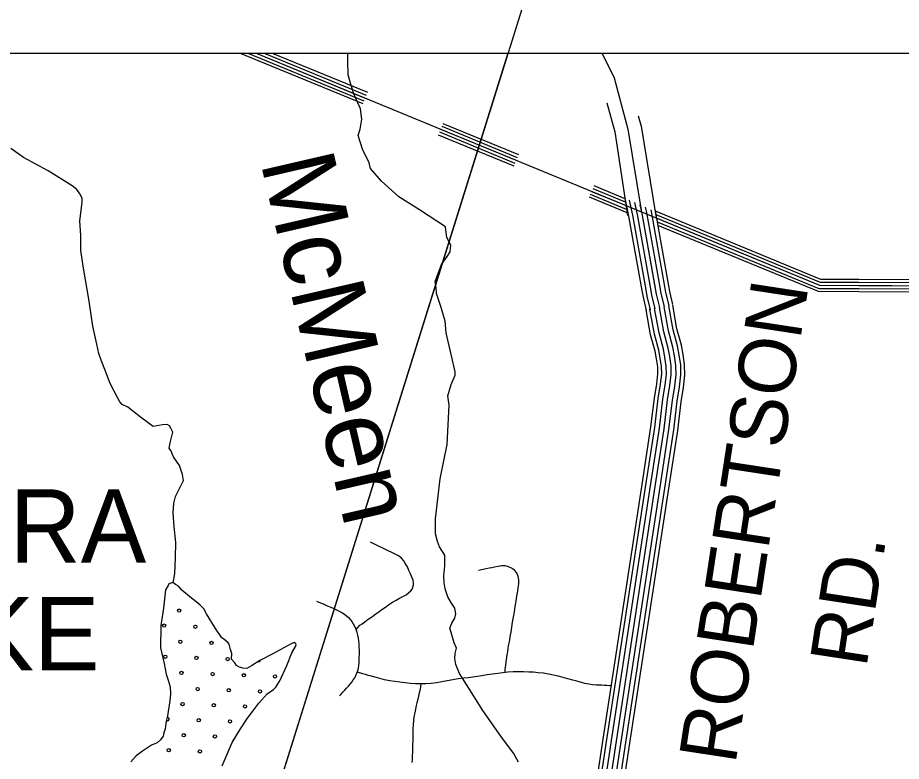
# Model space of a CAD drawing. Extents: x 1577619 to 1828281, y 483481 to 598136.
# Drawn here: x 1675660 to 1681374, y 521931 to 526740 of the extents above; entities that cross this region are included whole.
import ezdxf

# ---------------------------------------------------------------- set-up
doc = ezdxf.new("R2010")
doc.units = 0
for name, color, linetype in [('DESIGN - DRAINAGE - Bridges and Cross Drains Size Text', 7, 'Continuous'), ('DESIGN - ROW - Right-of-Way and Easement Labels', 7, 'Continuous'), ('DESIGN - SHEET - Linework', 7, 'Continuous'), ('DESIGN - TRAFFIC CONTROL PERMANENT - Pavement Marking Text', 7, 'Continuous'), ('DESIGN - TRANSPORTATION - Text', 7, 'Continuous'), ('SURVEY - CENTERLINE - Preliminary Text', 7, 'Continuous'), ('SURVEY - DRAINAGE - Natural Features', 7, 'Continuous'), ('SURVEY - PROPERTY - Owners', 7, 'Continuous'), ('SURVEY - TRANSPORTATION - Roads', 7, 'Continuous')]:
    doc.layers.add(name, color=color, linetype=linetype)

msp = doc.modelspace()

# ---------------------------------------------------------------- linework, layer by layer
at = {"layer": 'DESIGN - SHEET - Linework'}
msp.add_lwpolyline([(1669171.5, 526510.7), (1695618, 526510.7), (1695618, 508119.9), (1669171.5, 508119.9)], close=True, dxfattribs=at)
at = {"layer": 'DESIGN - TRAFFIC CONTROL PERMANENT - Pavement Marking Text'}
for centre in [(1676703.8, 522905.8), (1676606.8, 522808.7), (1676808.4, 522801.2), (1676711.3, 522704.2), (1676912.9, 522696.7), (1676614.2, 522607.1), (1676815.8, 522599.6), (1677017.4, 522592.2), (1676718.8, 522502.5), (1676920.4, 522495.1), (1677122, 522487.6), (1677323.6, 522480.1), (1676823.3, 522398), (1677024.9, 522390.5), (1677226.5, 522383.1), (1676726.2, 522300.9), (1676927.8, 522293.5), (1677129.5, 522286), (1676830.8, 522196.4), (1677032.4, 522188.9), (1676733.7, 522099.3), (1676935.3, 522091.9), (1676636.6, 522002.3), (1676838.2, 521994.8)]:
    msp.add_circle(centre, 10.6, dxfattribs=at)
for centre, start, end in [((1677219.1, 522584.7), 237.8609, 5.2046), ((1677420.7, 522577.2), 132.7109, 185.9701), ((1676629.2, 522203.9), 226.8297, 105.5304)]:
    msp.add_arc(centre, 10.6, start, end, dxfattribs=at)
at = {"layer": 'DESIGN - TRANSPORTATION - Text'}
for points in [[(1677941.4, 525764.7), (1677931.6, 525800.8), (1677888.5, 525889.7), (1677861.5, 525978.3), (1677874, 526018.4), (1677884.8, 526084.5), (1677875.5, 526150.9), (1677832.5, 526247.8), (1677811.3, 526316.3), (1677795.9, 526370.7), (1677794.9, 526457), (1677795.5, 526510.7)], [(1676664.8, 523084.7), (1676676.7, 523144.6), (1676679.8, 523246.9), (1676682.8, 523345.1), (1676671.9, 523449.5), (1676664.9, 523537.8), (1676669.5, 523599.9), (1676680, 523643.9), (1676712.7, 523707.8), (1676731.1, 523747.7), (1676725.5, 523785.8), (1676706.1, 523844.2), (1676666.7, 523900.8), (1676649.1, 523941.1), (1676639.3, 523955.2), (1676645.6, 523991.2), (1676662.4, 524059.2), (1676650.6, 524085.4), (1676640.8, 524099.6), (1676626.9, 524109.8), (1676596.8, 524106.1), (1676548.7, 524098.5), (1676536.7, 524096.7), (1676463.2, 524149.6), (1676371.9, 524220.7), (1676336.1, 524239.2), (1676320.2, 524255.4), (1676306.5, 524279.6), (1676257.5, 524374.3), (1676228.3, 524454.9), (1676199, 524525.4), (1676183.5, 524567.6), (1676172.1, 524627.9), (1676145.3, 524744.5), (1676121, 524907.2), (1676085.3, 525120.2), (1676068.5, 525234.7), (1676067.5, 525330.9), (1676062.5, 525425.2), (1676071.2, 525493.3), (1676075.8, 525549.4), (1676076, 525573.5), (1676062.3, 525599.7), (1676042.6, 525628), (1676010.9, 525652.4), (1675857.8, 525750.3), (1675696.6, 525836.2), (1675615.2, 525893.2)], [(1678449.3, 524235), (1678441.9, 524295.3), (1678462.7, 524367.2), (1678489.3, 524427.1), (1678489.6, 524449.2), (1678464.7, 524553.7), (1678430.2, 524702.5), (1678423, 524776.8), (1678397.9, 524865.3), (1678366.9, 524955.8), (1678365.3, 524996), (1678359.7, 525034.1), (1678380.3, 525092.1), (1678400.9, 525144), (1678437.4, 525195.7), (1678455.8, 525225.6), (1678460.2, 525269.7), (1678434.7, 525318.1), (1678431.1, 525350.2), (1678425.5, 525386.4), (1678257.5, 525498.2), (1678123.9, 525582), (1678013.1, 525683.7), (1677941.4, 525764.7)], [(1678899.1, 521926), (1678865.7, 521984.5), (1678782.8, 522093.7), (1678666.5, 522259.4), (1678562.2, 522426.9), (1678517, 522499.6), (1678493.5, 522556), (1678486, 522596.2), (1678488.3, 522628.2), (1678496.7, 522662.2), (1678483, 522696.5), (1678461.7, 522764.9), (1678454, 522793), (1678466.4, 522825), (1678486.7, 522856.9), (1678493, 522884.9), (1678487.4, 522921), (1678465.7, 522953.4), (1678442.1, 522993.7), (1678424.7, 523046), (1678417.1, 523084.2), (1678415.6, 523130.4), (1678422.3, 523194.5), (1678421, 523264.7), (1678387.5, 523317.2), (1678373.9, 523353.4), (1678360.4, 523401.7), (1678361.5, 523499.9), (1678392.2, 523758.3), (1678436.6, 523980.5), (1678449.3, 524235)], [(1676981.7, 521902.1), (1677047.3, 522051.8), (1677100.3, 522141.5), (1677145.1, 522209.2), (1677179.6, 522254.9), (1677218.1, 522306.7), (1677272.8, 522368.3), (1677313.2, 522395.9), (1677329.3, 522409.8), (1677355.5, 522450.8), (1677400.8, 522551.4), (1677431.7, 522633.3), (1677456.5, 522672.5), (1677461.4, 522684.8), (1677458.4, 522691.2), (1677446.4, 522699.3), (1677428.3, 522691.5), (1677309.6, 522626.6), (1677225.1, 522583.3), (1677170.7, 522547.8), (1677140.5, 522532.1), (1677116.5, 522534.4), (1677094.5, 522540.6), (1677074.6, 522550.8), (1677062.8, 522567), (1677043.1, 522591.3), (1677043.4, 522627.4), (1677035.7, 522653.5), (1677026.1, 522687.7), (1677018.2, 522699.8), (1676992.4, 522720.2), (1676980.5, 522730.3), (1676939.1, 522790.9), (1676880.1, 522885.8), (1676862.4, 522918.1), (1676836.7, 522942.4), (1676771.2, 522997.2), (1676721.6, 523037.9), (1676699.9, 523064.2), (1676680, 523074.4), (1676662.1, 523086.6), (1676638, 523078.8), (1676631.9, 523066.9), (1676615.5, 523039), (1676602.3, 522920.8), (1676585.1, 522808.7), (1676583.6, 522664.3), (1676606.5, 522563.8), (1676619.8, 522495.5), (1676633.4, 522455.2), (1676644.9, 522413), (1676648.4, 522366.8), (1676644, 522322.7), (1676628.9, 522224.6), (1676620.6, 522190.6), (1676614, 522140.5), (1676603.8, 522114.6), (1676599.5, 522092.6), (1676583.3, 522070.7), (1676561.1, 522050.9), (1676524.9, 522035.2), (1676466.4, 521997.7), (1676426.1, 521966), (1676391.7, 521928.3)]]:
    msp.add_lwpolyline(points, dxfattribs=at)
at = {"layer": 'SURVEY - CENTERLINE - Preliminary Text'}
for points in [[(1681695, 533313.3), (1681214.7, 531661.5), (1681112.7, 531483.8), (1680721.5, 531075.8), (1680358.7, 530689.6), (1680210.6, 530522.4), (1680066.1, 530306.8), (1679906.2, 529952.9), (1676801.4, 520023.1), (1676698.9, 519793.1), (1676511.6, 519505.7), (1675717.5, 518546.5)], [(1681695, 533313.3), (1681214.7, 531661.5), (1681112.7, 531483.8), (1680721.5, 531075.8), (1680358.7, 530689.6), (1680210.6, 530522.4), (1680066.1, 530306.8), (1679906.2, 529952.9), (1676801.4, 520023.1), (1676698.9, 519793.1), (1676511.6, 519505.7), (1675717.5, 518546.5)], [(1678829.9, 526510.7), (1676801.4, 520023.1), (1676698.9, 519793.1), (1676511.6, 519505.7), (1675717.5, 518546.5)], [(1678829.9, 526510.7), (1676801.4, 520023.1), (1676698.9, 519793.1), (1676511.6, 519505.7), (1675717.5, 518546.5)]]:
    msp.add_lwpolyline(points, dxfattribs=at)
at = {"layer": 'SURVEY - DRAINAGE - Natural Features'}
for points in [[(1677098.9, 526510.7), (1677890.8, 526184.3)], [(1677148.7, 526510.7), (1677898, 526201.9)], [(1677201.2, 526510.7), (1680843.7, 525009.3), (1682251, 525004.6), (1682499, 525306.4), (1681975.1, 526439.5), (1683586.7, 526280), (1683263.3, 526510.7)], [(1677201.2, 526510.7), (1680843.7, 525009.3), (1682251, 525004.6), (1682499, 525306.4), (1681975.1, 526439.5), (1683586.7, 526280), (1683263.3, 526510.7)], [(1677201.2, 526510.7), (1677905.6, 526220.4)], [(1677253.7, 526510.7), (1677913.3, 526238.8)], [(1677306.2, 526510.7), (1677920.9, 526257.3)], [(1678401.4, 526037.6), (1678889.6, 525836.4)], [(1678409, 526056.1), (1678897.2, 525854.9)], [(1678378.9, 525983.1), (1678867.1, 525781.9)], [(1678386.2, 526000.7), (1678874.3, 525799.4)], [(1678393.8, 526019.1), (1678881.9, 525817.9)], [(1679377.7, 525635.2), (1679588.8, 525548.2)], [(1679385.3, 525653.7), (1679585.5, 525571.2)], [(1679355.2, 525580.7), (1679599.3, 525480.1)], [(1679362.5, 525598.2), (1679595.2, 525502.3)], [(1679370.1, 525616.7), (1679593.7, 525524.5)], [(1679569.7, 525577.7), (1679584.5, 525571.6)], [(1681097.7, 524969.5), (1682269.4, 524965.6), (1682544.6, 525300.5), (1682406.7, 525598.9)], [(1681097.7, 524988.5), (1682260.5, 524984.6), (1682522.4, 525303.4), (1682389.5, 525590.9)], [(1681097.8, 525008.5), (1682251, 525004.6), (1682499, 525306.4), (1682371.3, 525582.5)], [(1681097.9, 525028.5), (1682241.6, 525024.7), (1682475.5, 525309.4), (1682353.2, 525574.1)], [(1681097.9, 525048.5), (1682232.2, 525044.7), (1682452.1, 525312.4), (1682335, 525565.7)], [(1679781.9, 525490.3), (1680851.7, 525049.3), (1681097.9, 525048.5)], [(1679785.4, 525467.2), (1680847.7, 525029.3), (1681097.9, 525028.5)], [(1679787.6, 525444.6), (1680843.7, 525009.3), (1681097.8, 525008.5)], [(1679794.4, 525420.2), (1680839.7, 524989.4), (1681097.7, 524988.5)], [(1679797.1, 525398.5), (1680835.9, 524970.4), (1681097.7, 524969.5)]]:
    msp.add_lwpolyline(points, dxfattribs=at)
at = {"layer": 'SURVEY - PROPERTY - Owners'}
for points in [[(1679694.9, 525476.7), (1679695.3, 525474), (1679788.8, 524950.9), (1679808.9, 524865)], [(1678966.7, 518137.3), (1678967.1, 518141.1), (1679244.6, 520161.6), (1679530.9, 522061.8), (1679782.5, 523707.6), (1679840.5, 524082), (1679862.5, 524268.3), (1679877.5, 524360.4), (1679886.2, 524432.5), (1679884.8, 524488.7), (1679875.8, 524548), (1679866, 524603.2), (1679837.1, 524707.8), (1679808.9, 524865)]]:
    msp.add_lwpolyline(points, dxfattribs=at)
at = {"layer": 'SURVEY - TRANSPORTATION - Roads'}
for points in [[(1679437.4, 526510.7), (1679443.9, 526498.7), (1679516.8, 526351.4), (1679606.1, 526019.1), (1679691.9, 525495.2)], [(1679469.8, 526190.2), (1679520.2, 526002.5), (1679602.4, 525461.6)], [(1679672.7, 526105.3), (1679690.9, 526037.4), (1679787.9, 525445.6)], [(1679585.3, 525572.9), (1679610.2, 525457.2), (1679696.2, 524976.1)], [(1679613.3, 525560.2), (1679634.5, 525462), (1679720.6, 524980.5)], [(1679648.4, 525544.6), (1679664.9, 525468), (1679751.1, 524985.9)], [(1679683.3, 525529.8), (1679695.3, 525474), (1679781.6, 524991.4)], [(1679693.3, 525483.5), (1679695.3, 525474), (1679788.8, 524950.9), (1679808.9, 524865)], [(1679718.2, 525515.1), (1679725.8, 525480), (1679812.1, 524996.8)], [(1679753.9, 525496.6), (1679756.2, 525486), (1679842.6, 525002.3)], [(1679779, 525502), (1679781.4, 525491), (1679868, 525006.8)], [(1679842.6, 525002.3), (1679849.6, 524963.4), (1679869.2, 524879)], [(1679867.9, 525006.8), (1679874.8, 524968.6), (1679894.3, 524884.9)], [(1679696.2, 524976.1), (1679703.9, 524933.4), (1679724.4, 524845.3)], [(1679720.6, 524980.5), (1679728.1, 524938.4), (1679748.5, 524850.9)], [(1679751.1, 524985.9), (1679758.5, 524944.7), (1679778.7, 524857.9)], [(1679781.6, 524991.4), (1679788.8, 524950.9), (1679808.9, 524865)], [(1679812.1, 524996.9), (1679819.2, 524957.2), (1679839.1, 524872)], [(1678913.3, 518386.8), (1679158.8, 520174), (1679445.2, 522074.8), (1679696.8, 523720.8), (1679754.6, 524093.8), (1679776.6, 524280.4), (1679791.6, 524372.6), (1679799.4, 524436.7), (1679798.3, 524481.1), (1679790.3, 524533.9), (1679781.4, 524584), (1679752.5, 524688.5), (1679723.5, 524849.6)], [(1678938.1, 518385.7), (1679183.3, 520170.5), (1679469.6, 522071.1), (1679721.2, 523717), (1679779.1, 524090.4), (1679801.1, 524276.9), (1679816.1, 524369.1), (1679824.1, 524435.5), (1679822.9, 524483.2), (1679814.7, 524537.9), (1679805.5, 524589.4), (1679776.6, 524694), (1679747.8, 524854)], [(1678966.7, 518137.3), (1678967.1, 518141.1), (1679244.6, 520161.6), (1679530.9, 522061.8), (1679782.5, 523707.6), (1679840.5, 524082), (1679862.5, 524268.3), (1679877.5, 524360.4), (1679886.2, 524432.5), (1679884.8, 524488.7), (1679875.8, 524548), (1679866, 524603.2), (1679837.1, 524707.8), (1679808.9, 524865)], [(1678969.1, 518383.4), (1679214, 520166), (1679500.3, 522066.4), (1679751.9, 523712.3), (1679809.8, 524086.2), (1679831.8, 524272.6), (1679846.8, 524364.8), (1679855.2, 524434), (1679853.9, 524486), (1679845.3, 524543), (1679835.8, 524596.3), (1679806.9, 524700.9), (1679778.4, 524859.5)], [(1679000, 518380.8), (1679244.6, 520161.6), (1679530.9, 522061.8), (1679782.5, 523707.6), (1679840.5, 524082), (1679862.5, 524268.3), (1679877.5, 524360.4), (1679886.2, 524432.5), (1679884.8, 524488.7), (1679875.8, 524548), (1679866, 524603.2), (1679837.1, 524707.8), (1679808.9, 524865)], [(1679031.1, 518379.3), (1679275.3, 520157.2), (1679561.6, 522057.1), (1679813.1, 523702.9), (1679871.2, 524077.8), (1679893.2, 524264), (1679908.2, 524356), (1679917.3, 524431), (1679915.8, 524491.4), (1679906.4, 524553), (1679896.3, 524610), (1679867.4, 524714.6), (1679839.4, 524870.5)], [(1679062.1, 518376.9), (1679306, 520152.8), (1679592.2, 522052.5), (1679843.8, 523698.2), (1679901.9, 524073.6), (1679923.9, 524259.7), (1679938.9, 524351.7), (1679948.3, 524429.5), (1679946.7, 524494.1), (1679937, 524558.1), (1679926.6, 524616.9), (1679897.6, 524721.5), (1679869.9, 524875.9)], [(1679087.5, 518373.1), (1679331.5, 520149.1), (1679617.7, 522048.6), (1679869.2, 523694.3), (1679927.4, 524070.2), (1679949.4, 524256.1), (1679964.3, 524348.1), (1679974.1, 524428.3), (1679972.4, 524496.4), (1679962.4, 524562.3), (1679951.7, 524622.6), (1679922.7, 524727.2), (1679895.2, 524880.5)], [(1677808.6, 522429.9), (1677819.4, 522443.3), (1677829.7, 522457.4), (1677838.7, 522471.9), (1677846.9, 522486.7), (1677853.5, 522501.6), (1677859, 522517.5), (1677863.1, 522534.2), (1677865.6, 522551), (1677867.3, 522569.2), (1677868.3, 522585.5), (1677868.8, 522602.6), (1677869, 522624.8), (1677869, 522647.8), (1677868.6, 522671.1), (1677867, 522693.6), (1677865.4, 522710.8), (1677863.2, 522727.9), (1677859.6, 522746.5), (1677855.3, 522764), (1677849.2, 522783.4), (1677873, 522811.5), (1677886.4, 522820.9), (1677904, 522833.4), (1677926.8, 522849.6), (1677942.3, 522860.3), (1677955.7, 522870), (1677974.6, 522883.7), (1677994.6, 522898), (1678015.2, 522913.1), (1678037.3, 522928.9), (1678060, 522944.3), (1678083, 522959.4), (1678106.6, 522973), (1678129, 522985.5), (1678150.7, 522997), (1678170.7, 523008.4), (1678189, 523021.7), (1678200.9, 523032.5), (1678210.6, 523045.1), (1678215.7, 523056.7), (1678219.7, 523072), (1678218.7, 523085.8), (1678216.2, 523102.6), (1678209.2, 523121.6), (1678199.4, 523143.2), (1678189.8, 523165.8), (1678179.3, 523187.8), (1678168, 523208.3), (1678156, 523227.7), (1678141.3, 523244.6), (1678122.5, 523259), (1678101, 523271.2), (1678078.5, 523282), (1678055.2, 523292.8), (1678033.7, 523303.2), (1678012.4, 523313.9), (1677997, 523321), (1677985.2, 523326.6), (1677940, 523347.4)], [(1678810.8, 522505), (1678812.4, 522527.7), (1678815.3, 522550.6), (1678818.8, 522574.9), (1678823, 522603.3), (1678825.8, 522622.2), (1678828.7, 522639.3), (1678832.1, 522662.9), (1678836.6, 522687.6), (1678841.3, 522714.9), (1678845.1, 522737.7), (1678849.8, 522767.2), (1678854.9, 522798.8), (1678860.2, 522831.2), (1678865.9, 522863.9), (1678871.3, 522898.4), (1678877.3, 522931.5), (1678882.6, 522965.6), (1678888, 522998.7), (1678893.1, 523030.3), (1678896.9, 523052.5), (1678900.1, 523079), (1678900.6, 523103.8), (1678895.8, 523127.1), (1678886.3, 523149.1), (1678871.6, 523166.7), (1678853, 523180.7), (1678833, 523189.6), (1678811.9, 523194.6), (1678788.8, 523194.4), (1678766.5, 523190.7), (1678743, 523186.2), (1678726.4, 523182.3), (1678708.5, 523179.2), (1678688.6, 523174.7), (1678639.6, 523165)], [(1677592.7, 522966.1), (1677638.8, 522946.7), (1677660.9, 522937.4), (1677684.6, 522927.4), (1677704.3, 522918.8), (1677721.5, 522910.6), (1677737.7, 522902.1), (1677755.1, 522892.4), (1677771.9, 522881.7), (1677785.5, 522871.4), (1677797.8, 522860.3), (1677809.3, 522848.2), (1677819.8, 522835), (1677829.5, 522821.1), (1677849.2, 522783.4)], [(1679494.9, 522418.2), (1679486.6, 522419), (1679469.4, 522420.3), (1679452.8, 522421.5), (1679436.5, 522422.4), (1679419, 522423.3), (1679401.5, 522424.2), (1679377.2, 522426.3), (1679353.8, 522429.5), (1679326.2, 522435.2), (1679298.7, 522442.4), (1679276.2, 522448.8), (1679250.2, 522456.3), (1679217.7, 522465), (1679187.5, 522473.3), (1679155.5, 522481.3), (1679124.1, 522488.2), (1679091, 522495), (1679058.7, 522500.1), (1679024.9, 522503.7), (1678994.1, 522506.6), (1678964.7, 522508.3), (1678930.3, 522509.4), (1678896.5, 522510.1), (1678863.6, 522509.3), (1678829.7, 522507.1), (1678797, 522503.4), (1678764.1, 522499), (1678730.8, 522494.3), (1678696.3, 522489.2), (1678661.3, 522484), (1678632.1, 522479.6), (1678602.7, 522475.2), (1678573.3, 522471.1), (1678543.9, 522469.6), (1678508, 522464.5), (1678472.6, 522457.5), (1678437.5, 522450.6), (1678402.1, 522444), (1678366.8, 522439.3), (1678332.6, 522434.9), (1678298.8, 522432.7), (1678266.1, 522432.3), (1678232.3, 522433), (1678197.9, 522434.4), (1678164.4, 522437.7), (1678131.5, 522442), (1678098.7, 522446.3), (1678066.4, 522451.8), (1678032.6, 522458.3), (1678000.4, 522465.9), (1677972.2, 522474.2), (1677946.5, 522480.6), (1677925.5, 522487), (1677908.9, 522491.6), (1677890.6, 522497.2), (1677857.2, 522507.4)], [(1677740.9, 522354.3), (1677748.9, 522363.2), (1677763.9, 522379.8), (1677774.7, 522392.1), (1677786.4, 522404.7), (1677798.1, 522417.7), (1677808.6, 522429.9)], [(1678266.1, 522432.3), (1678265.4, 522415.9), (1678261.3, 522394.8), (1678256.1, 522373.4), (1678250.8, 522352.7), (1678244.3, 522324.8), (1678240.6, 522308.4), (1678236.8, 522291.3), (1678231.9, 522268.5), (1678226.9, 522244.1), (1678221.9, 522219.4), (1678218.7, 522194), (1678216.3, 522167.8), (1678215.2, 522141.2), (1678214.6, 522115), (1678214.6, 522089.2), (1678213.8, 522064.4), (1678213.3, 522038.9), (1678212.4, 522015.7), (1678211.9, 521991.3), (1678211.1, 521967.3), (1678210.2, 521944.3), (1678209.4, 521922.5)]]:
    msp.add_lwpolyline(points, dxfattribs=at)

# ---------------------------------------------------------------- texts
at = {"layer": 'DESIGN - DRAINAGE - Bridges and Cross Drains Size Text'}
for s, height, rotation, p in [('McMeen', 475.01, 283.0376, (1677229.1, 525806.6)), ('LAURA', 475.19, 0, (1674372.2, 523215)), ('LAKE', 475.19, 0, (1674564.4, 522519.4))]:
    msp.add_text(s, height=height, rotation=rotation, dxfattribs=at).set_placement(p)
at = {"layer": 'DESIGN - ROW - Right-of-Way and Easement Labels'}
for s, p in [('ROBERTSON', (1680300.3, 521906)), ('RD.', (1681147.2, 522530))]:
    msp.add_text(s, height=370.01, rotation=81.3096, dxfattribs=at).set_placement(p)

doc.saveas('drawing.dxf')
